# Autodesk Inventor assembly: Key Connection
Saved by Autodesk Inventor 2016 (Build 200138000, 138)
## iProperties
Created: 2015-08
Part Number: Key Connection
Document SubType Name: Assembly
Designer: stank
ClientObjectVersion: 1
Author: stank
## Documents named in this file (2)
- E:\Turbokompr\Sklop turbokompresora\Design Accelerator\Key Connection6.iam
- C:\Users\stank\Documents\Inventor\Content Center Files\R2016\en-US\ISO 2491 - A\ISO 2491 - A  8 x 5 x 20.ipt
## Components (1 placed, 1 different names)
1. ISO 2491 A A  8 x 5 x 20:1
